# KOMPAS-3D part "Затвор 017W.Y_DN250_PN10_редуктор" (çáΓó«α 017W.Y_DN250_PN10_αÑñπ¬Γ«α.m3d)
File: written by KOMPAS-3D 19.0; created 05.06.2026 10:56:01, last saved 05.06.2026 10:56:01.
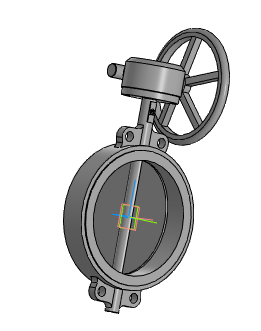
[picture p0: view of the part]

Document properties: Автор: Энергия; Полное имя файла: ..\..\..\3d для проектировщиков\x.x Тип 017W.Y(S) Затвор дисковый поворотный межфланцевый\Затвор 017W.Y(S)_DN50-DN1200_редуктор\Затвор 017W.Y_DN250_PN10_редуктор.a3d

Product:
- Part/product: Затвор 017W.Y_DN250_PN10_редуктор
    Масса: 30.8383

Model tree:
1. Операция без истории:1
